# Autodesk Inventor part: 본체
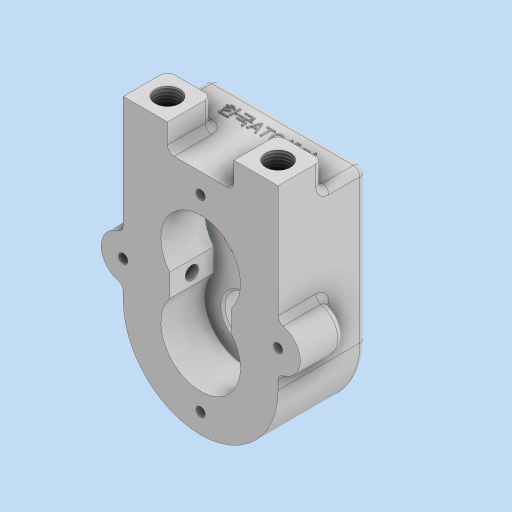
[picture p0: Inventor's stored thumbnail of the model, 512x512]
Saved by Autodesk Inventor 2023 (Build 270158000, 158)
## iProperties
Created: 2024-03
Part Number: 본체
Material: 일반
Document SubType Name: Modeling
Designer: asung
Density: 1 g/cm^3
Appearance: 기본값
Author: asung
## Parameters: d1 = 68 mm, d4 = 0, d5 = 12 mm, d9 = 12 mm, d11 = 0, d12 = 63.5 mm, d15 = 0, d16 = 36 mm, d17 = 33 mm, d18 = 36 mm, d19 = 14 mm, d20 = 14 mm, d22 = 0, d59 = 52 mm, d60 = 6 mm, d61 = 0, d62 = 32 mm, d63 = 4 mm, d64 = 0, d65 = 15 mm, d66 = 6 mm, d69 = 90 deg, d71 = 0, d72 = 15 mm, d73 = 6 mm, d74 = 25 mm, d75 = 7.3 mm, d76 = 90 deg, d78 = 0, d89 = 6 mm, d90 = 4 mm, d91 = 2 mm, d92 = 90 deg, d94 = 0, d95 = 60 deg, d96 = 7 mm, d97 = 90 deg, d98 = 3 mm, d99 = 1 mm, d100 = 2 mm, d101 = 45 deg, d102 = 42 mm, d103 = 3.242 mm, d104 = 8 mm, d105 = 4 mm, d106 = 2 mm, d107 = 90 deg, d109 = 118 deg, d111 = 360 deg, d113 = 0.7 mm, d114 = 2 mm, d115 = 30 deg, d120 = 10.5 mm, d121 = 11 mm, d122 = 0.62479 mm, d123 = 10.589 mm, d124 = 3.023 mm, d125 = 2 mm, d126 = 82 deg, d127 = 16 mm, d128 = 0, d129 = 25 mm, d130 = 25 mm, d135 = 6 mm, d136 = 0, d137 = 0, d138 = 1 mm, d139 = 2 mm, d140 = 30 deg, d141 = 1 mm, d142 = 2 mm, d143 = 30 deg, d144 = 26 mm, d145 = 26 mm, d146 = 4.134 mm, d148 = 4 mm, d149 = 2 mm, d150 = 90 deg, d151 = 12 mm, d152 = 118 deg, d154 = 8 mm, d155 = 3 mm, d156 = 3 mm, d157 = 3 mm, d158 = 3 mm, d160 = 3 mm, d161 = 1 mm, d162 = 2 mm, d163 = 30 deg, d165 = 0.5 mm, d166 = 0, d167 = 3 mm
